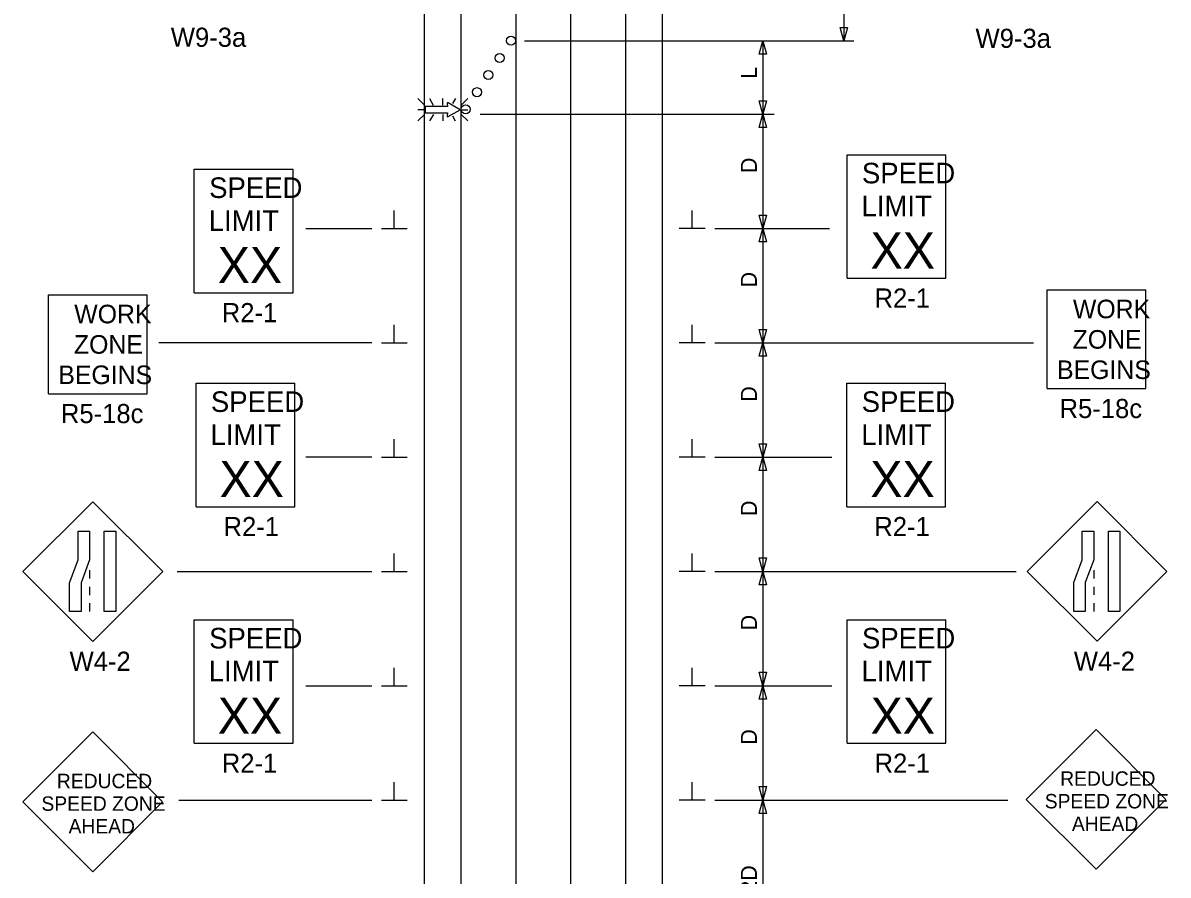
# Model space of a CAD drawing. Extents: x 16648 to 18482, y 5650 to 7013.
# Drawn here: x 16728 to 17229, y 6193 to 6566 of the extents above; entities that cross this region are included whole.
import ezdxf

# ---------------------------------------------------------------- set-up
doc = ezdxf.new("R2010")
doc.units = 0
for name, color, linetype in [('ALI_LEGAL_EX', 7, 'Continuous'), ('PAVT_EDGE_EX', 7, 'Continuous'), ('TRAFFIC_SIGNS_PR', 7, 'Continuous'), ('TYPICAL_TEXT_DIMEN_PR', 7, 'Continuous')]:
    doc.layers.add(name, color=color, linetype=linetype)

msp = doc.modelspace()

# ---------------------------------------------------------------- linework, layer by layer
at = {"layer": 'ALI_LEGAL_EX'}
for p, q in [((16943.36, 7013.47), (16943.36, 6195.33)), ((16967.36, 7013.47), (16967.36, 6195.33)), ((16943.36, 6961.56), (16943.36, 6097.65)), ((16967.36, 6961.56), (16967.36, 6097.65))]:
    msp.add_line(p, q, dxfattribs=at)
for points in [[(16943.36, 6524.34), (16943.36, 6499.34)], [(16943.36, 6524.34), (16943.36, 6499.34)], [(16943.36, 6524.34), (16943.36, 6499.34)], [(16943.36, 6524.34), (16943.36, 6499.34)], [(16943.36, 6524.34), (16943.36, 6499.34)], [(16967.36, 6524.34), (16967.36, 6499.34)], [(16967.36, 6524.34), (16967.36, 6499.34)], [(16967.36, 6524.34), (16967.36, 6499.34)], [(16967.36, 6524.34), (16967.36, 6499.34)], [(16967.36, 6524.34), (16967.36, 6499.34)], [(16943.36, 6424.34), (16943.36, 6399.34)], [(16943.36, 6424.34), (16943.36, 6399.34)], [(16943.36, 6424.34), (16943.36, 6399.34)], [(16943.36, 6424.34), (16943.36, 6399.34)], [(16943.36, 6424.34), (16943.36, 6399.34)], [(16967.36, 6424.34), (16967.36, 6399.34)], [(16967.36, 6424.34), (16967.36, 6399.34)], [(16967.36, 6424.34), (16967.36, 6399.34)], [(16967.36, 6424.34), (16967.36, 6399.34)], [(16967.36, 6424.34), (16967.36, 6399.34)], [(16943.36, 6324.34), (16943.36, 6299.34)], [(16943.36, 6324.34), (16943.36, 6299.34)], [(16943.36, 6324.34), (16943.36, 6299.34)], [(16943.36, 6324.34), (16943.36, 6299.34)], [(16943.36, 6324.34), (16943.36, 6299.34)], [(16967.36, 6324.34), (16967.36, 6299.34)], [(16967.36, 6324.34), (16967.36, 6299.34)], [(16967.36, 6324.34), (16967.36, 6299.34)], [(16967.36, 6324.34), (16967.36, 6299.34)], [(16967.36, 6324.34), (16967.36, 6299.34)], [(16943.36, 6224.34), (16943.36, 6199.34)], [(16943.36, 6224.34), (16943.36, 6199.34)], [(16943.36, 6224.34), (16943.36, 6199.34)], [(16943.36, 6224.34), (16943.36, 6199.34)], [(16967.36, 6224.34), (16967.36, 6199.34)], [(16967.36, 6224.34), (16967.36, 6199.34)], [(16967.36, 6224.34), (16967.36, 6199.34)], [(16967.36, 6224.34), (16967.36, 6199.34)], [(16967.36, 6224.34), (16967.36, 6199.34)]]:
    msp.add_lwpolyline(points, dxfattribs=at)
at = {"layer": 'PAVT_EDGE_EX'}
for p, q in [((16903.36, 6926.44), (16903.36, 5975.16)), ((16919.36, 6926.44), (16919.36, 5975.16)), ((16991.36, 6926.44), (16991.36, 5975.16)), ((17007.36, 6926.44), (17007.36, 5975.16))]:
    msp.add_line(p, q, dxfattribs=at)
at = {"layer": 'TRAFFIC_SIGNS_PR'}
for p, q in [((16903.38, 6530.22), (16900.56, 6533.04)), ((16905.67, 6533.04), (16907.3, 6530.22)), ((16911.46, 6530.22), (16911.46, 6533.04)), ((16916.93, 6533.04), (16915.72, 6530.95)), ((16922.37, 6533.04), (16919.55, 6530.22)), ((16903.38, 6528.19), (16900.56, 6528.19)), ((16903.38, 6526.16), (16900.56, 6523.34)), ((16907.33, 6526.16), (16905.7, 6523.34)), ((16911.46, 6526.16), (16911.46, 6523.34)), ((16915.65, 6525.52), (16916.91, 6523.34)), ((16919.55, 6528.19), (16922.37, 6528.19)), ((16922.37, 6523.34), (16919.55, 6526.16)), ((17088.24, 6508.51), (17131.44, 6508.51)), ((17088.24, 6454.51), (17088.24, 6508.51)), ((17131.44, 6454.51), (17131.44, 6508.51)), ((16802.78, 6502.12), (16845.98, 6502.12)), ((16802.78, 6448.12), (16802.78, 6502.12)), ((16845.98, 6448.12), (16845.98, 6502.12)), ((17088.24, 6454.51), (17131.44, 6454.51)), ((16739.04, 6403.98), (16739.04, 6447.18)), ((16739.04, 6447.18), (16782.24, 6447.18)), ((16782.24, 6403.98), (16782.24, 6447.18)), ((16802.78, 6448.12), (16845.98, 6448.12)), ((17175.75, 6406.19), (17175.75, 6449.39)), ((17175.75, 6449.39), (17218.95, 6449.39)), ((17218.95, 6406.19), (17218.95, 6449.39)), ((16803.55, 6408.54), (16846.75, 6408.54)), ((16803.55, 6354.54), (16803.55, 6408.54)), ((16846.75, 6354.54), (16846.75, 6408.54)), ((17088.13, 6408.54), (17131.33, 6408.54)), ((17088.13, 6354.54), (17088.13, 6408.54)), ((17131.33, 6354.54), (17131.33, 6408.54)), ((17175.75, 6406.19), (17218.95, 6406.19)), ((16739.04, 6403.98), (16782.24, 6403.98)), ((16758.41, 6356.72), (16727.86, 6326.17)), ((16788.96, 6326.17), (16758.41, 6356.72)), ((17197.57, 6356.77), (17167.02, 6326.22)), ((17228.11, 6326.22), (17197.57, 6356.77)), ((16803.55, 6354.54), (16846.75, 6354.54)), ((17088.13, 6354.54), (17131.33, 6354.54)), ((16727.86, 6326.17), (16758.41, 6295.63)), ((16757.01, 6326.73), (16757.01, 6323.13)), ((16758.41, 6295.63), (16788.96, 6326.17)), ((17167.02, 6326.22), (17197.57, 6295.67)), ((17196.16, 6326.77), (17196.16, 6323.17)), ((17197.57, 6295.67), (17228.11, 6326.22)), ((16757.01, 6319.53), (16757.01, 6315.93)), ((17196.16, 6319.57), (17196.16, 6315.97)), ((16757.01, 6312.33), (16757.01, 6308.73)), ((17196.16, 6312.37), (17196.16, 6308.77)), ((16802.78, 6305.07), (16845.98, 6305.07)), ((16802.78, 6251.07), (16802.78, 6305.07)), ((16845.98, 6251.07), (16845.98, 6305.07)), ((17088.26, 6305.07), (17131.46, 6305.07)), ((17088.26, 6251.07), (17088.26, 6305.07)), ((17131.46, 6251.07), (17131.46, 6305.07)), ((16758.38, 6256.01), (16727.83, 6225.46)), ((16788.92, 6225.46), (16758.38, 6256.01)), ((17197.12, 6257.06), (17166.57, 6226.51)), ((17227.66, 6226.51), (17197.12, 6257.06)), ((16802.78, 6251.07), (16845.98, 6251.07)), ((17088.26, 6251.07), (17131.46, 6251.07)), ((16727.83, 6225.46), (16758.38, 6194.91)), ((16758.38, 6194.91), (16788.92, 6225.46)), ((17166.57, 6226.51), (17197.12, 6195.97)), ((17197.12, 6195.97), (17227.66, 6226.51))]:
    msp.add_line(p, q, dxfattribs=at)
for points in [[(16913.29, 6530.87), (16913.52, 6529.58), (16903.8, 6529.58), (16903.8, 6526.83), (16913.52, 6526.83), (16913.29, 6525.53)], [(16913.79, 6525.18), (16919.1, 6528.19), (16913.79, 6531.23)]]:
    msp.add_lwpolyline(points, dxfattribs=at)
for points in [[(16757.01, 6343.88), (16757.01, 6331.3), (16753.24, 6321.3), (16753.24, 6308.73), (16748.19, 6308.73), (16748.19, 6321.3), (16751.95, 6331.3), (16751.95, 6343.88)], [(16768.41, 6343.88), (16768.41, 6308.73), (16763.35, 6308.73), (16763.35, 6343.88)], [(17196.16, 6343.92), (17196.16, 6331.34), (17192.4, 6321.35), (17192.4, 6308.77), (17187.35, 6308.77), (17187.35, 6321.35), (17191.11, 6331.34), (17191.11, 6343.92)], [(17207.57, 6343.92), (17207.57, 6308.77), (17202.51, 6308.77), (17202.51, 6343.92)]]:
    msp.add_lwpolyline(points, close=True, dxfattribs=at)
for centre in [(16941.29, 6558.37), (16936.33, 6550.85), (16931.36, 6543.35), (16926.39, 6535.85), (16921.42, 6528.34)]:
    msp.add_circle(centre, 2, dxfattribs=at)
for centre, start, end in [((16913.62, 6530.93), 61.4833, 189.9593), ((16913.62, 6525.47), 170.7308, 298.8916)]:
    msp.add_arc(centre, 0.341, start, end, dxfattribs=at)
at = {"layer": 'TYPICAL_TEXT_DIMEN_PR'}
for p, q in [((17086.84, 6676.24), (17086.84, 6558.37)), ((17086.84, 6558.37), (17085.27, 6564.23)), ((17085.27, 6564.23), (17086.84, 6564.23)), ((17086.84, 6564.23), (17088.41, 6564.23)), ((17088.41, 6564.23), (17086.84, 6558.37)), ((16947.11, 6558.37), (17091.17, 6558.37)), ((17049.79, 6552.51), (17051.36, 6558.37)), ((17051.36, 6558.37), (17051.36, 6526.26)), ((17051.36, 6558.37), (17052.93, 6552.51)), ((17051.36, 6552.51), (17049.79, 6552.51)), ((17052.93, 6552.51), (17051.36, 6552.51)), ((17051.36, 6526.26), (17049.79, 6532.12)), ((17049.79, 6532.12), (17051.36, 6532.12)), ((17051.36, 6532.12), (17052.93, 6532.12)), ((17052.93, 6532.12), (17051.36, 6526.26)), ((16927.76, 6526.26), (17056.36, 6526.26)), ((17049.79, 6520.4), (17051.36, 6526.26)), ((17051.36, 6526.26), (17051.36, 6476.26)), ((17051.36, 6526.26), (17052.93, 6520.4)), ((17051.36, 6520.4), (17049.79, 6520.4)), ((17052.93, 6520.4), (17051.36, 6520.4)), ((16890.23, 6476.26), (16890.23, 6484.05)), ((17020.48, 6476.26), (17020.48, 6484.05)), ((17051.36, 6476.26), (17049.79, 6482.12)), ((17049.79, 6482.12), (17051.36, 6482.12)), ((17051.36, 6482.12), (17052.93, 6482.12)), ((17052.93, 6482.12), (17051.36, 6476.26)), ((16851.49, 6476.26), (16880.36, 6476.26)), ((16884.61, 6476.26), (16895.86, 6476.26)), ((17026.11, 6476.26), (17014.86, 6476.26)), ((17030.36, 6476.26), (17080.52, 6476.26)), ((17049.79, 6470.4), (17051.36, 6476.26)), ((17051.36, 6476.26), (17051.36, 6426.26)), ((17051.36, 6476.26), (17052.93, 6470.4)), ((17051.36, 6470.4), (17049.79, 6470.4)), ((17052.93, 6470.4), (17051.36, 6470.4)), ((16890.23, 6426.26), (16890.23, 6434.05)), ((17020.48, 6426.26), (17020.48, 6434.05)), ((17051.36, 6426.26), (17049.79, 6432.12)), ((17049.79, 6432.12), (17051.36, 6432.12)), ((17051.36, 6432.12), (17052.93, 6432.12)), ((17052.93, 6432.12), (17051.36, 6426.26)), ((16880.36, 6426.26), (16787.26, 6426.26)), ((16884.61, 6426.26), (16895.86, 6426.26)), ((17026.11, 6426.26), (17014.86, 6426.26)), ((17030.36, 6426.26), (17169.69, 6426.26)), ((17030.36, 6426.26), (17095.61, 6426.26)), ((17049.79, 6420.4), (17051.36, 6426.26)), ((17051.36, 6426.26), (17052.93, 6420.4)), ((17051.36, 6426.26), (17051.36, 6376.26)), ((17051.36, 6420.4), (17049.79, 6420.4)), ((17052.93, 6420.4), (17051.36, 6420.4)), ((16890.23, 6376.26), (16890.23, 6384.05)), ((17020.48, 6376.26), (17020.48, 6384.05)), ((17051.36, 6376.26), (17049.79, 6382.12)), ((17049.79, 6382.12), (17051.36, 6382.12)), ((17051.36, 6382.12), (17052.93, 6382.12)), ((17052.93, 6382.12), (17051.36, 6376.26)), ((16880.36, 6376.26), (16851.49, 6376.26)), ((16884.61, 6376.26), (16895.86, 6376.26)), ((17026.11, 6376.26), (17014.86, 6376.26)), ((17030.36, 6376.26), (17081.54, 6376.26)), ((17049.79, 6370.4), (17051.36, 6376.26)), ((17051.36, 6376.26), (17051.36, 6326.26)), ((17051.36, 6376.26), (17052.93, 6370.4)), ((17051.36, 6370.4), (17049.79, 6370.4)), ((17052.93, 6370.4), (17051.36, 6370.4)), ((16890.23, 6326.26), (16890.23, 6334.05)), ((17020.48, 6326.26), (17020.48, 6334.05)), ((17051.36, 6326.26), (17049.79, 6332.12)), ((17049.79, 6332.12), (17051.36, 6332.12)), ((17051.36, 6332.12), (17052.93, 6332.12)), ((17052.93, 6332.12), (17051.36, 6326.26)), ((16795.32, 6326.26), (16880.36, 6326.26)), ((16884.61, 6326.26), (16895.86, 6326.26)), ((17026.11, 6326.26), (17014.86, 6326.26)), ((17030.36, 6326.26), (17162.19, 6326.26)), ((17049.79, 6320.4), (17051.36, 6326.26)), ((17051.36, 6326.26), (17051.36, 6276.26)), ((17051.36, 6326.26), (17052.93, 6320.4)), ((17051.36, 6320.4), (17049.79, 6320.4)), ((17052.93, 6320.4), (17051.36, 6320.4)), ((16890.23, 6276.26), (16890.23, 6284.05)), ((17020.48, 6276.26), (17020.48, 6284.05)), ((17051.36, 6276.26), (17049.79, 6282.12)), ((17049.79, 6282.12), (17051.36, 6282.12)), ((17051.36, 6282.12), (17052.93, 6282.12)), ((17052.93, 6282.12), (17051.36, 6276.26)), ((16851.49, 6276.26), (16880.36, 6276.26)), ((16884.61, 6276.26), (16895.86, 6276.26)), ((17026.11, 6276.26), (17014.86, 6276.26)), ((17030.36, 6276.26), (17081.54, 6276.26)), ((17049.79, 6270.4), (17051.36, 6276.26)), ((17051.36, 6276.26), (17051.36, 6226.26)), ((17051.36, 6276.26), (17052.93, 6270.4)), ((17051.36, 6270.4), (17049.79, 6270.4)), ((17052.93, 6270.4), (17051.36, 6270.4)), ((16890.23, 6226.26), (16890.23, 6234.05)), ((17020.48, 6226.26), (17020.48, 6234.05)), ((17051.36, 6226.26), (17049.79, 6232.12)), ((17049.79, 6232.12), (17051.36, 6232.12)), ((17051.36, 6232.12), (17052.93, 6232.12)), ((17052.93, 6232.12), (17051.36, 6226.26)), ((16795.95, 6226.26), (16880.36, 6226.26)), ((16884.61, 6226.26), (16895.86, 6226.26)), ((17026.11, 6226.26), (17014.86, 6226.26)), ((17030.36, 6226.26), (17158.6, 6226.26)), ((17049.79, 6220.4), (17051.36, 6226.26)), ((17051.36, 6226.26), (17051.36, 6151.26)), ((17051.36, 6226.26), (17052.93, 6220.4)), ((17051.36, 6220.4), (17049.79, 6220.4)), ((17052.93, 6220.4), (17051.36, 6220.4))]:
    msp.add_line(p, q, dxfattribs=at)

# ---------------------------------------------------------------- texts
at = {"layer": 'TRAFFIC_SIGNS_PR'}
for s, height, p in [('W9-3a', 8.37, (16792.51, 6555.71)), ('W9-3a', 8.37, (17144.41, 6555.24)), ('SPEED', 9, (17094.72, 6495.98)), ('SPEED', 9, (16809.27, 6489.59)), ('LIMIT', 9, (17094.54, 6481.58)), ('LIMIT', 9, (16809.09, 6475.19)), ('XX', 15.785, (17098.49, 6458.74)), ('XX', 15.785, (16813.03, 6452.35)), ('R2-1', 8.37, (17100.25, 6441.64)), ('WORK', 8.119, (17187, 6436.98)), ('WORK', 8.119, (16750.29, 6434.77)), ('R2-1', 8.37, (16814.79, 6435.25)), ('ZONE', 8.119, (17186.87, 6423.69)), ('ZONE', 8.119, (16750.15, 6421.48)), ('BEGINS', 8.119, (16743.32, 6408.19)), ('BEGINS', 8.119, (17180.04, 6410.41)), ('SPEED', 9, (16810.03, 6396.01)), ('SPEED', 9, (17094.62, 6396.01)), ('R5-18c', 8.37, (17181.16, 6393.32)), ('R5-18c', 8.37, (16744.45, 6391.11)), ('LIMIT', 9, (16809.85, 6381.61)), ('LIMIT', 9, (17094.44, 6381.61)), ('XX', 15.785, (16813.8, 6358.77)), ('XX', 15.785, (17098.38, 6358.77)), ('R2-1', 8.37, (16815.56, 6341.67)), ('R2-1', 8.37, (17100.14, 6341.67)), ('SPEED', 9, (16809.27, 6292.54)), ('SPEED', 9, (17094.74, 6292.54)), ('W4-2', 8.37, (16748.24, 6282.76)), ('W4-2', 8.37, (17187.39, 6282.8)), ('LIMIT', 9, (16809.09, 6278.14)), ('LIMIT', 9, (17094.56, 6278.14)), ('XX', 15.785, (16813.03, 6255.3)), ('XX', 15.785, (17098.51, 6255.3)), ('R2-1', 8.37, (16814.79, 6238.2)), ('R2-1', 8.37, (17100.27, 6238.2)), ('REDUCED', 6.3, (16742.69, 6231.43)), ('REDUCED', 6.3, (17181.43, 6232.49)), ('SPEED ZONE', 6.3, (16735.93, 6221.53)), ('SPEED ZONE', 6.3, (17174.67, 6222.59)), ('AHEAD', 6.3, (16747.81, 6211.63)), ('AHEAD', 6.3, (17186.55, 6212.69))]:
    msp.add_text(s, height=height, dxfattribs=at).set_placement(p)
at = {"layer": 'TYPICAL_TEXT_DIMEN_PR'}
for s, p in [('L', (17048.8, 6541.67)), ('D', (17048.8, 6500.48)), ('D', (17048.8, 6450.48)), ('D', (17048.8, 6400.48)), ('D', (17048.8, 6350.48)), ('D', (17048.8, 6300.48)), ('D', (17048.8, 6250.48)), ('2D', (17048.8, 6185.73))]:
    msp.add_text(s, height=7, rotation=90, dxfattribs=at).set_placement(p)

doc.saveas('drawing.dxf')
